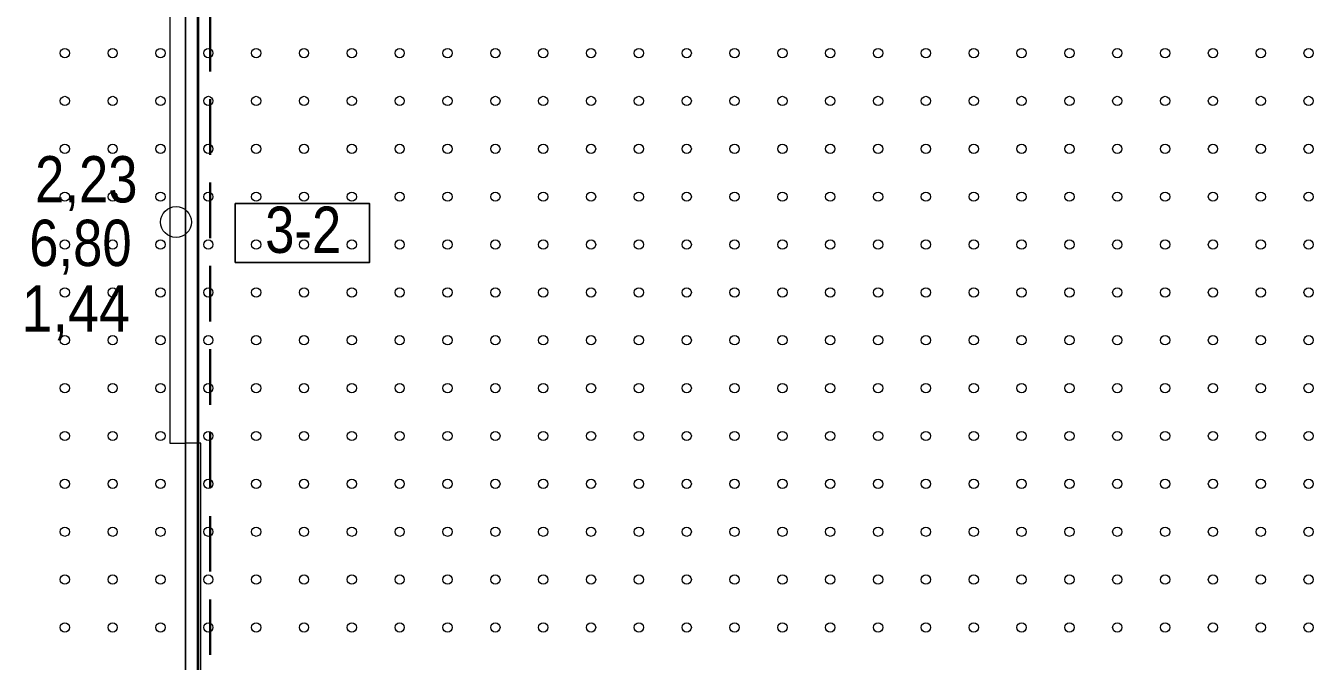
# Model space of a CAD drawing. Extents: x 640104 to 640970, y 6442278 to 6442689.
# Drawn here: x 640160 to 640243.4, y 6442585.9 to 6442627 of the extents above; entities that cross this region are included whole.
import ezdxf
from ezdxf.enums import TextEntityAlignment as Align

# ---------------------------------------------------------------- set-up
doc = ezdxf.new("R2010")
doc.units = 0
doc.header["$LTSCALE"] = 1.2
doc.linetypes.add('MEDIUM_DASHED', pattern=[4.5, 3, -1.5])
for name, color, linetype, lineweight in [('32', 7, 'Continuous', 25), ('33', 7, 'Continuous', 13), ('35', 7, 'Continuous', 35), ('43', 7, 'Continuous', 13), ('47', 7, 'Continuous', 13)]:
    doc.layers.add(name, color=color, linetype=linetype, lineweight=lineweight)

msp = doc.modelspace()

# ---------------------------------------------------------------- linework, layer by layer
at = {"layer": '32'}
msp.add_line((640170.36, 6442660), (640170.36, 6442540), dxfattribs=at)
at = {"layer": '33'}
for points in [[(640169.36, 6442630), (640169.36, 6442600), (640170.36, 6442600), (640170.36, 6442630)], [(640171.36, 6442565), (640171.36, 6442600), (640170.36, 6442600), (640170.36, 6442565)]]:
    msp.add_lwpolyline(points, close=True, dxfattribs=at)
at = {"layer": '33', "lineweight": 25}
msp.add_lwpolyline([(640173.59, 6442615.52), (640182.3, 6442615.52), (640182.3, 6442611.72), (640173.59, 6442611.72)], close=True, dxfattribs=at)
at = {"layer": '35', "lineweight": 40}
msp.add_line((640171.16, 6442655.36), (640171.16, 6442545.53), dxfattribs=at)
at = {"layer": '35', "linetype": 'MEDIUM_DASHED'}
msp.add_line((640171.96, 6442654.69), (640171.96, 6442565.61), dxfattribs=at)
at = {"layer": '43'}
for centre in [(640162.549, 6442625.273), (640165.649, 6442625.273), (640168.749, 6442625.273), (640171.849, 6442625.273), (640174.949, 6442625.273), (640178.049, 6442625.273), (640181.149, 6442625.273), (640184.249, 6442625.273), (640187.349, 6442625.273), (640190.449, 6442625.273), (640193.549, 6442625.273), (640196.649, 6442625.273), (640199.749, 6442625.273), (640202.849, 6442625.273), (640205.949, 6442625.273), (640209.049, 6442625.273), (640212.149, 6442625.273), (640215.249, 6442625.273), (640218.349, 6442625.273), (640221.449, 6442625.273), (640224.549, 6442625.273), (640227.649, 6442625.273), (640230.749, 6442625.273), (640233.849, 6442625.273), (640236.949, 6442625.273), (640240.049, 6442625.273), (640243.149, 6442625.273), (640162.549, 6442622.173), (640165.649, 6442622.173), (640168.749, 6442622.173), (640171.849, 6442622.173), (640174.949, 6442622.173), (640178.049, 6442622.173), (640181.149, 6442622.173), (640184.249, 6442622.173), (640187.349, 6442622.173), (640190.449, 6442622.173), (640193.549, 6442622.173), (640196.649, 6442622.173), (640199.749, 6442622.173), (640202.849, 6442622.173), (640205.949, 6442622.173), (640209.049, 6442622.173), (640212.149, 6442622.173), (640215.249, 6442622.173), (640218.349, 6442622.173), (640221.449, 6442622.173), (640224.549, 6442622.173), (640227.649, 6442622.173), (640230.749, 6442622.173), (640233.849, 6442622.173), (640236.949, 6442622.173), (640240.049, 6442622.173), (640243.149, 6442622.173), (640162.549, 6442619.073), (640165.649, 6442619.073), (640168.749, 6442619.073), (640171.849, 6442619.073), (640174.949, 6442619.073), (640178.049, 6442619.073), (640181.149, 6442619.073), (640184.249, 6442619.073), (640187.349, 6442619.073), (640190.449, 6442619.073), (640193.549, 6442619.073), (640196.649, 6442619.073), (640199.749, 6442619.073), (640202.849, 6442619.073), (640205.949, 6442619.073), (640209.049, 6442619.073), (640212.149, 6442619.073), (640215.249, 6442619.073), (640218.349, 6442619.073), (640221.449, 6442619.073), (640224.549, 6442619.073), (640227.649, 6442619.073), (640230.749, 6442619.073), (640233.849, 6442619.073), (640236.949, 6442619.073), (640240.049, 6442619.073), (640243.149, 6442619.073), (640162.549, 6442615.973), (640165.649, 6442615.973), (640168.749, 6442615.973), (640171.849, 6442615.973), (640174.949, 6442615.973), (640178.049, 6442615.973), (640181.149, 6442615.973), (640184.249, 6442615.973), (640187.349, 6442615.973), (640190.449, 6442615.973), (640193.549, 6442615.973), (640196.649, 6442615.973), (640199.749, 6442615.973), (640202.849, 6442615.973), (640205.949, 6442615.973), (640209.049, 6442615.973), (640212.149, 6442615.973), (640215.249, 6442615.973), (640218.349, 6442615.973), (640221.449, 6442615.973), (640224.549, 6442615.973), (640227.649, 6442615.973), (640230.749, 6442615.973), (640233.849, 6442615.973), (640236.949, 6442615.973), (640240.049, 6442615.973), (640243.149, 6442615.973), (640162.549, 6442612.873), (640165.649, 6442612.873), (640168.749, 6442612.873), (640171.849, 6442612.873), (640174.949, 6442612.873), (640178.049, 6442612.873), (640181.149, 6442612.873), (640184.249, 6442612.873), (640187.349, 6442612.873), (640190.449, 6442612.873), (640193.549, 6442612.873), (640196.649, 6442612.873), (640199.749, 6442612.873), (640202.849, 6442612.873), (640205.949, 6442612.873), (640209.049, 6442612.873), (640212.149, 6442612.873), (640215.249, 6442612.873), (640218.349, 6442612.873), (640221.449, 6442612.873), (640224.549, 6442612.873), (640227.649, 6442612.873), (640230.749, 6442612.873), (640233.849, 6442612.873), (640236.949, 6442612.873), (640240.049, 6442612.873), (640243.149, 6442612.873), (640162.549, 6442609.773), (640165.649, 6442609.773), (640168.749, 6442609.773), (640171.849, 6442609.773), (640174.949, 6442609.773), (640178.049, 6442609.773), (640181.149, 6442609.773), (640184.249, 6442609.773), (640187.349, 6442609.773), (640190.449, 6442609.773), (640193.549, 6442609.773), (640196.649, 6442609.773), (640199.749, 6442609.773), (640202.849, 6442609.773), (640205.949, 6442609.773), (640209.049, 6442609.773), (640212.149, 6442609.773), (640215.249, 6442609.773), (640218.349, 6442609.773), (640221.449, 6442609.773), (640224.549, 6442609.773), (640227.649, 6442609.773), (640230.749, 6442609.773), (640233.849, 6442609.773), (640236.949, 6442609.773), (640240.049, 6442609.773), (640243.149, 6442609.773), (640162.549, 6442606.673), (640165.649, 6442606.673), (640168.749, 6442606.673), (640171.849, 6442606.673), (640174.949, 6442606.673), (640178.049, 6442606.673), (640181.149, 6442606.673), (640184.249, 6442606.673), (640187.349, 6442606.673), (640190.449, 6442606.673), (640193.549, 6442606.673), (640196.649, 6442606.673), (640199.749, 6442606.673), (640202.849, 6442606.673), (640205.949, 6442606.673), (640209.049, 6442606.673), (640212.149, 6442606.673), (640215.249, 6442606.673), (640218.349, 6442606.673), (640221.449, 6442606.673), (640224.549, 6442606.673), (640227.649, 6442606.673), (640230.749, 6442606.673), (640233.849, 6442606.673), (640236.949, 6442606.673), (640240.049, 6442606.673), (640243.149, 6442606.673), (640162.549, 6442603.573), (640165.649, 6442603.573), (640168.749, 6442603.573), (640171.849, 6442603.573), (640174.949, 6442603.573), (640178.049, 6442603.573), (640181.149, 6442603.573), (640184.249, 6442603.573), (640187.349, 6442603.573), (640190.449, 6442603.573), (640193.549, 6442603.573), (640196.649, 6442603.573), (640199.749, 6442603.573), (640202.849, 6442603.573), (640205.949, 6442603.573), (640209.049, 6442603.573), (640212.149, 6442603.573), (640215.249, 6442603.573), (640218.349, 6442603.573), (640221.449, 6442603.573), (640224.549, 6442603.573), (640227.649, 6442603.573), (640230.749, 6442603.573), (640233.849, 6442603.573), (640236.949, 6442603.573), (640240.049, 6442603.573), (640243.149, 6442603.573), (640162.549, 6442600.473), (640165.649, 6442600.473), (640168.749, 6442600.473), (640171.849, 6442600.473), (640174.949, 6442600.473), (640178.049, 6442600.473), (640181.149, 6442600.473), (640184.249, 6442600.473), (640187.349, 6442600.473), (640190.449, 6442600.473), (640193.549, 6442600.473), (640196.649, 6442600.473), (640199.749, 6442600.473), (640202.849, 6442600.473), (640205.949, 6442600.473), (640209.049, 6442600.473), (640212.149, 6442600.473), (640215.249, 6442600.473), (640218.349, 6442600.473), (640221.449, 6442600.473), (640224.549, 6442600.473), (640227.649, 6442600.473), (640230.749, 6442600.473), (640233.849, 6442600.473), (640236.949, 6442600.473), (640240.049, 6442600.473), (640243.149, 6442600.473), (640162.549, 6442597.373), (640165.649, 6442597.373), (640168.749, 6442597.373), (640171.849, 6442597.373), (640174.949, 6442597.373), (640178.049, 6442597.373), (640181.149, 6442597.373), (640184.249, 6442597.373), (640187.349, 6442597.373), (640190.449, 6442597.373), (640193.549, 6442597.373), (640196.649, 6442597.373), (640199.749, 6442597.373), (640202.849, 6442597.373), (640205.949, 6442597.373), (640209.049, 6442597.373), (640212.149, 6442597.373), (640215.249, 6442597.373), (640218.349, 6442597.373), (640221.449, 6442597.373), (640224.549, 6442597.373), (640227.649, 6442597.373), (640230.749, 6442597.373), (640233.849, 6442597.373), (640236.949, 6442597.373), (640240.049, 6442597.373), (640243.149, 6442597.373), (640162.549, 6442594.273), (640165.649, 6442594.273), (640168.749, 6442594.273), (640171.849, 6442594.273), (640174.949, 6442594.273), (640178.049, 6442594.273), (640181.149, 6442594.273), (640184.249, 6442594.273), (640187.349, 6442594.273), (640190.449, 6442594.273), (640193.549, 6442594.273), (640196.649, 6442594.273), (640199.749, 6442594.273), (640202.849, 6442594.273), (640205.949, 6442594.273), (640209.049, 6442594.273), (640212.149, 6442594.273), (640215.249, 6442594.273), (640218.349, 6442594.273), (640221.449, 6442594.273), (640224.549, 6442594.273), (640227.649, 6442594.273), (640230.749, 6442594.273), (640233.849, 6442594.273), (640236.949, 6442594.273), (640240.049, 6442594.273), (640243.149, 6442594.273), (640162.549, 6442591.173), (640165.649, 6442591.173), (640168.749, 6442591.173), (640171.849, 6442591.173), (640174.949, 6442591.173), (640178.049, 6442591.173), (640181.149, 6442591.173), (640184.249, 6442591.173), (640187.349, 6442591.173), (640190.449, 6442591.173), (640193.549, 6442591.173), (640196.649, 6442591.173), (640199.749, 6442591.173), (640202.849, 6442591.173), (640205.949, 6442591.173), (640209.049, 6442591.173), (640212.149, 6442591.173), (640215.249, 6442591.173), (640218.349, 6442591.173), (640221.449, 6442591.173), (640224.549, 6442591.173), (640227.649, 6442591.173), (640230.749, 6442591.173), (640233.849, 6442591.173), (640236.949, 6442591.173), (640240.049, 6442591.173), (640243.149, 6442591.173), (640162.549, 6442588.073), (640165.649, 6442588.073), (640168.749, 6442588.073), (640171.849, 6442588.073), (640174.949, 6442588.073), (640178.049, 6442588.073), (640181.149, 6442588.073), (640184.249, 6442588.073), (640187.349, 6442588.073), (640190.449, 6442588.073), (640193.549, 6442588.073), (640196.649, 6442588.073), (640199.749, 6442588.073), (640202.849, 6442588.073), (640205.949, 6442588.073), (640209.049, 6442588.073), (640212.149, 6442588.073), (640215.249, 6442588.073), (640218.349, 6442588.073), (640221.449, 6442588.073), (640224.549, 6442588.073), (640227.649, 6442588.073), (640230.749, 6442588.073), (640233.849, 6442588.073), (640236.949, 6442588.073), (640240.049, 6442588.073), (640243.149, 6442588.073)]:
    msp.add_circle(centre, 0.3, dxfattribs=at)
at = {"layer": '47'}
msp.add_circle((640169.756, 6442614.33), 1, dxfattribs=at)

# ---------------------------------------------------------------- texts
at = {"layer": '33'}
for s, width, p in [('2,23', 0.85, (640163.94, 6442615.6)), ('3-2', 0.85, (640177.995, 6442612.33)), ('6,80', 0.85, (640163.56, 6442611.48)), ('1,44', 0.9, (640163.255, 6442607.23))]:
    msp.add_text(s, height=3, dxfattribs=dict(at, width=width)).set_placement(p, align=Align.CENTER)

doc.saveas('drawing.dxf')
